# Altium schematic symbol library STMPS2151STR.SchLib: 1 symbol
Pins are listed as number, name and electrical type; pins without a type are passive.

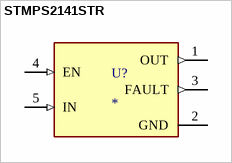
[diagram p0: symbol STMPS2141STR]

## STMPS2141STR
designator U?
Power Switch/Driver 1:1 N-Channel 500mA SOT-23-5; MP: STMPS2141STR; MF: STMicroelectronics
footprint STMPS2151STR
pins: 1 OUT (out), 2 GND (power), 3 FAULT (out), 4 EN (in), 5 IN (in)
